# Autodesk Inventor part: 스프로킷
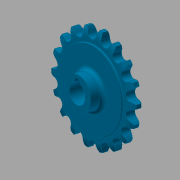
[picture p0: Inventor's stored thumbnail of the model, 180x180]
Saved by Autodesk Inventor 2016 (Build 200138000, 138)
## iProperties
Created: 2016-03
Part Number: 스프로킷
Material: 강철, 탄소
Document SubType Name: Modeling
Designer: mduedu
Density: 7.87 g/cm^3
Mass: 301.818 g
Surface Area: 124.882 cm^2
Volume: 38.3505 cm^3
Appearance: 하늘색 중간
Author: mduedu
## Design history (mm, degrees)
sketch "스케치1"
  geometry: L1 (0, 5)-(29.5, 5); L2 (29.5, 5)-(29.5, 4.1); L3 (30, 3.6)-(33.625, 3.6); L4 (40, 2)-(40, 0); L5 (40, 0)-(0, 0); L6 (0, 0)-(0, 5); L7 (0, -5)-(29.5, -5); L8 (29.5, -5)-(29.5, -4.1); L9 (30, -3.6)-(33.625, -3.6); L10 (40, -2)-(40, 0); L11 (0, 0)-(0, -5); A1 r 13.5 centre (33.625, -9.9) between (40, 2) and (33.625, 3.6); A2 r 13.5 centre (33.625, 9.9) between (33.625, -3.6) and (40, -2); A3 r 0.5 centre (30, 4.1) between (29.5, 4.1) and (30, 3.6); A4 r 0.5 centre (30, -4.1) between (30, -3.6) and (29.5, -4.1); 2 further points
  constraints: 22 end point, 8 point on circle, 6 symmetric about line, 5 tangent, 4 centre point, 4 parallel, 4 point on line, 1 equal radius, 1 horizontal, 1 perpendicular, 1 other
  dimensions: "d0" = 80 diameter of L4 L6; "d2" = 59 diameter of L2 L6; "d3" = 1.6 vertical distance of L4.start L3.end; "d4" = 3.6 distance from line of L4.end L3; "d5" = 5 distance between parallel lines of L5 L1; "d6" = 13.5 radius of A1; "d15" = 0.5 radius of A3
revolve "회전1" sketch "스케치1" stored, may be unused: angle "d7" = 90 deg
sketch "스케치2" dims "d8" = 65.2, "d11" = 80
  geometry: L1 (0, 0)-(0, 32.6); A1 r 36.57 centre (0, 0) between (-16.231, 32.771) and (0, 36.57); A2 r 3.97 centre (0, 36.57) between (-3.866, 35.665) and (0, 32.6); A3 r 12.7 centre (-16.231, 32.771) between (-3.866, 35.665) and (-5.534, 39.615); A4 r 12.7 centre (16.231, 32.771) between (5.534, 39.615) and (3.866, 35.665); A5 r 3.97 centre (0, 36.57) between (0, 32.6) and (3.866, 35.665); A6 r 40 centre (0, 0) between (5.534, 39.615) and (-5.534, 39.615); 2 further points
  constraints: 12 point on circle, 6 centre point, 4 coincident, 3 symmetric about line, 2 end point, 1 point on line, 1 tangent, 1 vertical, 1 vertical alignment, 7 other
  dimensions: "d10" = 73.14 diameter of A1; "d12" = 12.7 radius of A3
extrude "돌출1" cut sketch "스케치2" stored distance "d13" = 10; taper "d14" = 0 deg
sketch "스케치3"
  geometry: C1 r 12.5 at (0, 0); 1 further point
  constraints: 1 centre point, 1 coincident
  dimensions: "d19" = 25 diameter of C1
extrude "돌출2" join sketch "스케치3" distance "d20" = 10; taper "d21" = 0 deg
fillet "모깎기1" dims "d22" = 3
sketch "스케치4"
  geometry: L1 (-2.5, 0)-(2.5, 0); L2 (2.5, 0)-(2.5, 9.8); L3 (2.5, 9.8)-(-2.5, 9.8); L4 (-2.5, 9.8)-(-2.5, 0); C1 r 7.5 at (0, 0); 2 further points
  constraints: 8 end point, 2 coincident, 2 parallel, 1 centre point, 1 horizontal, 1 midpoint, 1 perpendicular
  dimensions: "d23" = 15 diameter of C1; "d25" = 5 distance of L2.end L3.end; "d26" = 9.8 distance of L1.end L2.end
extrude "돌출3" cut sketch "스케치4" stored distance "d27" = 8; taper "d28" = 0 deg
node "솔리드1"
pattern_circular "원형 패턴1" dims angle "d17" = 360 deg
